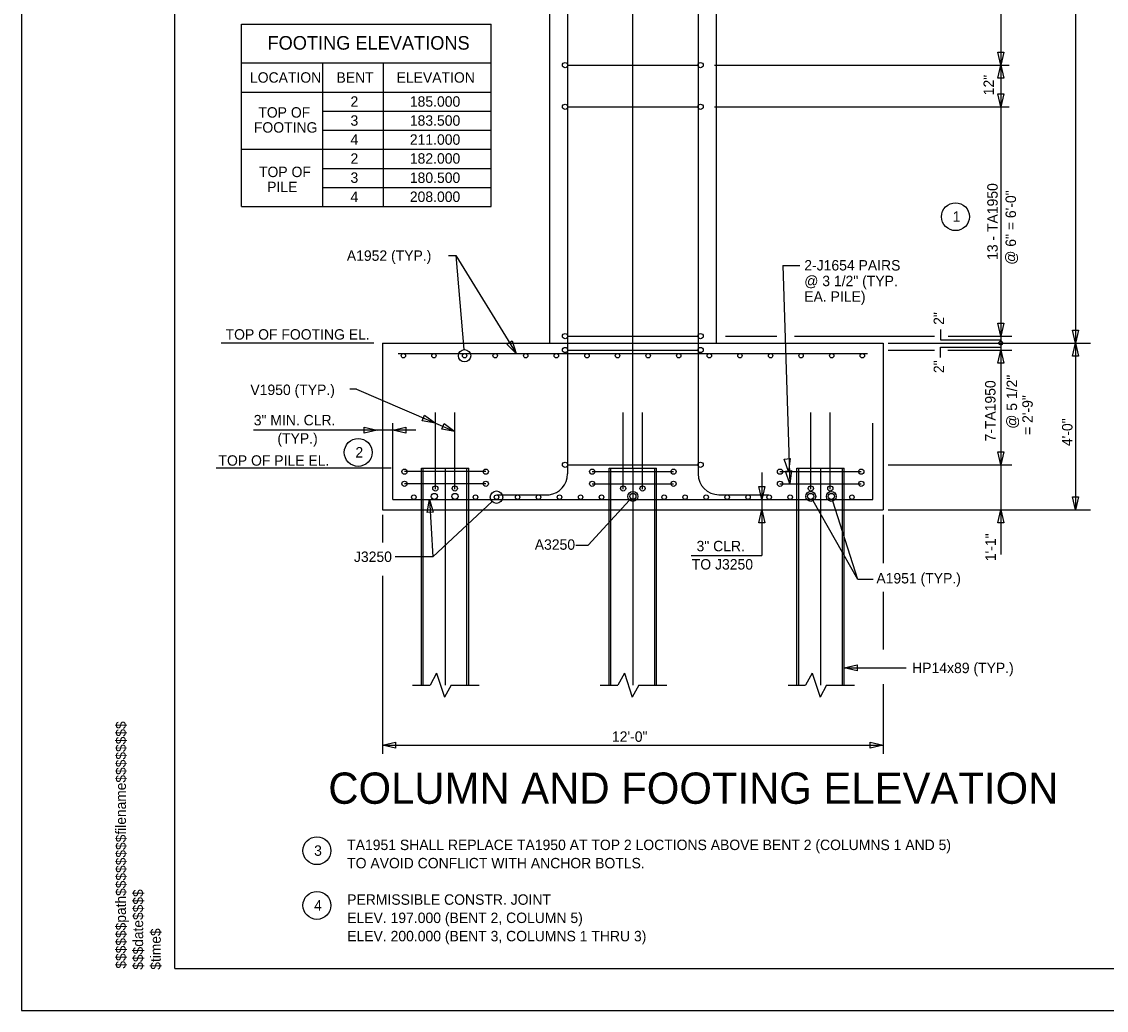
# Model space of a CAD drawing. Extents: x 1970675.2 to 1970711.3, y 796145.2 to 796167.2.
# Drawn here: x 1970675.24 to 1970688.23, y 796145.25 to 796157.1 of the extents above; entities that cross this region are included whole.
import ezdxf

# ---------------------------------------------------------------- set-up
doc = ezdxf.new("R2010")
doc.units = 0
for name, color, linetype in [('BR_AUTO DIMENSION', 7, 'Continuous'), ('BR_BORDER LINES', 7, 'Continuous'), ('BR_CENTER LINES', 7, 'Continuous'), ('BR_CONCRETE', 7, 'Continuous'), ('BR_REBAR', 7, 'Continuous'), ('BR_STRUCTURAL STEEL', 7, 'Continuous'), ('BR_TABLE LINES', 7, 'Continuous'), ('BR_TEXT', 7, 'Continuous'), ('Level 31', 7, 'Continuous'), ('RD_SHT_ID', 7, 'Continuous')]:
    doc.layers.add(name, color=color, linetype=linetype)

msp = doc.modelspace()

# ---------------------------------------------------------------- linework, layer by layer
at = {"layer": 'BR_AUTO DIMENSION'}
for p, q in [((1970686.97, 796164.857), (1970686.97, 796153.247)), ((1970687.866, 796162.732), (1970687.866, 796153.247)), ((1970683.541, 796156.581), (1970687.071, 796156.581)), ((1970683.541, 796156.081), (1970687.071, 796156.081)), ((1970680.352, 796154.299), (1970680.438, 796154.299)), ((1970680.438, 796154.299), (1970680.537, 796153.17)), ((1970680.438, 796154.299), (1970681.164, 796153.122)), ((1970684.356, 796154.176), (1970684.563, 796154.176)), ((1970684.356, 796154.176), (1970684.443, 796151.56)), ((1970686.247, 796153.41), (1970686.247, 796153.285)), ((1970679.456, 796153.247), (1970677.627, 796153.247)), ((1970683.669, 796153.331), (1970684.288, 796153.331)), ((1970684.499, 796153.331), (1970686.175, 796153.331)), ((1970685.621, 796153.247), (1970688.046, 796153.247)), ((1970686.247, 796153.285), (1970686.97, 796153.285)), ((1970686.34, 796153.331), (1970687.103, 796153.331)), ((1970686.97, 796153.247), (1970686.97, 796150.712)), ((1970687.866, 796153.247), (1970687.866, 796151.247)), ((1970685.621, 796153.164), (1970686.175, 796153.164)), ((1970686.247, 796153.074), (1970686.247, 796153.199)), ((1970686.247, 796153.199), (1970686.97, 796153.199)), ((1970686.335, 796153.164), (1970687.103, 796153.164)), ((1970679.25, 796152.695), (1970679.17, 796152.695)), ((1970679.25, 796152.695), (1970680.427, 796152.187)), ((1970679.959, 796152.203), (1970678.013, 796152.203)), ((1970679.666, 796151.747), (1970677.569, 796151.747)), ((1970684.106, 796151.695), (1970684.106, 796150.702)), ((1970684.106, 796151.695), (1970684.106, 796150.702)), ((1970685.621, 796151.789), (1970687.103, 796151.789)), ((1970686.97, 796151.747), (1970686.97, 796151.631)), ((1970680.123, 796151.372), (1970680.165, 796150.683)), ((1970680.873, 796151.349), (1970680.165, 796150.683)), ((1970682.024, 796150.825), (1970682.52, 796151.365)), ((1970685.258, 796150.414), (1970684.722, 796151.357)), ((1970685.258, 796150.414), (1970684.957, 796151.352)), ((1970679.561, 796151.187), (1970679.561, 796150.856)), ((1970685.561, 796151.187), (1970685.561, 796150.609)), ((1970685.621, 796151.247), (1970688.046, 796151.247)), ((1970681.879, 796150.825), (1970682.024, 796150.825)), ((1970680.165, 796150.683), (1970679.711, 796150.683)), ((1970683.258, 796150.702), (1970684.106, 796150.702)), ((1970683.265, 796150.702), (1970684.106, 796150.702)), ((1970679.561, 796150.458), (1970679.561, 796150.274)), ((1970685.441, 796150.414), (1970685.258, 796150.414)), ((1970679.561, 796150.274), (1970679.561, 796148.324)), ((1970685.561, 796150.263), (1970685.561, 796149.575)), ((1970685.094, 796149.355), (1970685.837, 796149.355)), ((1970680.209, 796149.288), (1970680.13, 796149.144)), ((1970680.209, 796149.288), (1970680.304, 796149)), ((1970682.459, 796149.288), (1970682.38, 796149.144)), ((1970682.459, 796149.288), (1970682.554, 796149)), ((1970684.709, 796149.288), (1970684.63, 796149.144)), ((1970684.709, 796149.288), (1970684.804, 796149)), ((1970679.92, 796149.144), (1970680.13, 796149.144)), ((1970680.382, 796149.144), (1970680.304, 796149)), ((1970680.382, 796149.144), (1970680.718, 796149.144)), ((1970682.17, 796149.144), (1970682.38, 796149.144)), ((1970682.632, 796149.144), (1970682.554, 796149)), ((1970682.632, 796149.144), (1970682.968, 796149.144)), ((1970684.42, 796149.144), (1970684.63, 796149.144)), ((1970684.882, 796149.144), (1970684.804, 796149)), ((1970684.882, 796149.144), (1970685.218, 796149.144)), ((1970685.561, 796149.158), (1970685.561, 796148.324)), ((1970679.561, 796148.426), (1970685.561, 796148.426))]:
    msp.add_line(p, q, dxfattribs=at)
for points in [[(1970687.006, 796156.737), (1970686.97, 796156.581), (1970686.934, 796156.737)], [(1970686.934, 796156.425), (1970686.97, 796156.581), (1970687.006, 796156.425)], [(1970687.006, 796156.237), (1970686.97, 796156.081), (1970686.934, 796156.237)], [(1970687.006, 796153.487), (1970686.97, 796153.331), (1970686.934, 796153.487)], [(1970687.902, 796153.403), (1970687.866, 796153.247), (1970687.83, 796153.403)], [(1970681.113, 796153.274), (1970681.164, 796153.122), (1970681.051, 796153.236)], [(1970687.83, 796153.091), (1970687.866, 796153.247), (1970687.902, 796153.091)], [(1970686.934, 796153.008), (1970686.97, 796153.164), (1970687.006, 796153.008)], [(1970680.065, 796152.382), (1970680.194, 796152.287), (1970680.036, 796152.316)], [(1970679.342, 796152.239), (1970679.498, 796152.203), (1970679.342, 796152.167)], [(1970679.842, 796152.167), (1970679.686, 796152.203), (1970679.842, 796152.239)], [(1970680.298, 796152.282), (1970680.427, 796152.187), (1970680.27, 796152.216)], [(1970687.006, 796151.945), (1970686.97, 796151.789), (1970686.934, 796151.945)], [(1970684.444, 796151.865), (1970684.426, 796151.706), (1970684.372, 796151.856)], [(1970684.461, 796151.719), (1970684.443, 796151.56), (1970684.389, 796151.71)], [(1970684.142, 796151.528), (1970684.106, 796151.372), (1970684.07, 796151.528)], [(1970680.096, 796151.214), (1970680.123, 796151.372), (1970680.168, 796151.219)], [(1970687.902, 796151.403), (1970687.866, 796151.247), (1970687.83, 796151.403)], [(1970684.07, 796151.091), (1970684.106, 796151.247), (1970684.142, 796151.091)], [(1970684.07, 796151.091), (1970684.106, 796151.247), (1970684.142, 796151.091)], [(1970686.934, 796151.091), (1970686.97, 796151.247), (1970687.006, 796151.091)], [(1970685.25, 796149.319), (1970685.094, 796149.355), (1970685.25, 796149.391)], [(1970679.717, 796148.39), (1970679.561, 796148.426), (1970679.717, 796148.462)], [(1970685.405, 796148.462), (1970685.561, 796148.426), (1970685.405, 796148.39)]]:
    msp.add_lwpolyline(points, close=True, dxfattribs=at)
for centre, radius in [((1970686.427, 796154.763), 0.167), ((1970686.97, 796153.247), 0.0235), ((1970679.269, 796151.936), 0.167), ((1970678.774, 796147.16), 0.167), ((1970678.774, 796146.504), 0.167)]:
    msp.add_circle(centre, radius, dxfattribs=at)
at = {"layer": 'BR_BORDER LINES'}
for q in [(1970677.07, 796166.746), (1970710.736, 796145.746)]:
    msp.add_line((1970677.07, 796145.746), q, dxfattribs=at)
at = {"layer": 'BR_CENTER LINES'}
for p, q in [((1970682.561, 796151.747), (1970682.561, 796166.409)), ((1970680.311, 796151.747), (1970680.311, 796149.144)), ((1970682.561, 796151.747), (1970682.561, 796149.144)), ((1970684.811, 796151.747), (1970684.811, 796149.144))]:
    msp.add_line(p, q, dxfattribs=at)
at = {"layer": 'BR_CONCRETE'}
for p, q in [((1970681.561, 796162.732), (1970681.561, 796153.247)), ((1970683.561, 796162.732), (1970683.561, 796153.247)), ((1970679.561, 796153.247), (1970685.561, 796153.247)), ((1970679.561, 796153.247), (1970679.561, 796151.247)), ((1970685.561, 796153.247), (1970685.561, 796151.247)), ((1970679.561, 796151.247), (1970685.561, 796151.247))]:
    msp.add_line(p, q, dxfattribs=at)
at = {"layer": 'BR_REBAR'}
for p, q in [((1970681.779, 796164.961), (1970681.779, 796154.623)), ((1970683.342, 796164.959), (1970683.342, 796151.679)), ((1970681.779, 796156.581), (1970683.342, 796156.581)), ((1970681.779, 796156.081), (1970683.342, 796156.081)), ((1970681.779, 796154.623), (1970681.779, 796151.678)), ((1970681.779, 796153.331), (1970683.342, 796153.331)), ((1970679.748, 796153.122), (1970685.373, 796153.122)), ((1970681.779, 796153.164), (1970683.342, 796153.164)), ((1970680.194, 796151.497), (1970680.194, 796152.417)), ((1970680.427, 796151.497), (1970680.427, 796152.417)), ((1970682.444, 796151.497), (1970682.444, 796152.417)), ((1970682.677, 796151.497), (1970682.677, 796152.417)), ((1970684.694, 796151.497), (1970684.694, 796152.417)), ((1970684.927, 796151.497), (1970684.927, 796152.417)), ((1970679.686, 796151.372), (1970679.686, 796152.289)), ((1970685.436, 796151.372), (1970685.436, 796152.289)), ((1970680.798, 796151.706), (1970679.824, 796151.706)), ((1970681.779, 796151.788), (1970683.342, 796151.788)), ((1970682.074, 796151.706), (1970683.048, 796151.706)), ((1970684.324, 796151.706), (1970685.298, 796151.706)), ((1970680.798, 796151.56), (1970679.824, 796151.56)), ((1970682.074, 796151.56), (1970683.048, 796151.56)), ((1970684.324, 796151.56), (1970685.298, 796151.56)), ((1970680.936, 796151.429), (1970681.557, 796151.429)), ((1970683.592, 796151.429), (1970684.185, 796151.429)), ((1970679.686, 796151.372), (1970685.436, 796151.372))]:
    msp.add_line(p, q, dxfattribs=at)
for centre, radius in [((1970681.748, 796156.581), 0.0313), ((1970683.373, 796156.581), 0.0313), ((1970681.748, 796156.081), 0.0313), ((1970683.373, 796156.081), 0.0313), ((1970681.748, 796153.331), 0.0313), ((1970683.373, 796153.331), 0.0313), ((1970679.811, 796153.096), 0.0265), ((1970680.177, 796153.096), 0.0265), ((1970680.544, 796153.096), 0.0265), ((1970680.911, 796153.096), 0.0265), ((1970681.277, 796153.096), 0.0265), ((1970681.644, 796153.096), 0.0265), ((1970681.748, 796153.164), 0.0313), ((1970682.011, 796153.096), 0.0265), ((1970682.377, 796153.096), 0.0265), ((1970682.744, 796153.096), 0.0265), ((1970683.111, 796153.096), 0.0265), ((1970683.373, 796153.164), 0.0313), ((1970683.477, 796153.096), 0.0265), ((1970683.844, 796153.096), 0.0265), ((1970684.211, 796153.096), 0.0265), ((1970684.577, 796153.096), 0.0265), ((1970684.944, 796153.096), 0.0265), ((1970685.311, 796153.096), 0.0265), ((1970685.311, 796153.096), 0.0265), ((1970681.748, 796151.788), 0.0313), ((1970683.373, 796151.788), 0.0313), ((1970679.824, 796151.706), 0.0313), ((1970680.798, 796151.706), 0.0313), ((1970682.074, 796151.706), 0.0313), ((1970683.048, 796151.706), 0.0313), ((1970684.324, 796151.706), 0.0313), ((1970685.298, 796151.706), 0.0313), ((1970679.824, 796151.56), 0.0313), ((1970680.798, 796151.56), 0.0313), ((1970682.074, 796151.56), 0.0313), ((1970683.048, 796151.56), 0.0313), ((1970684.324, 796151.56), 0.0313), ((1970685.298, 796151.56), 0.0313), ((1970679.936, 796151.4), 0.0265), ((1970680.182, 796151.409), 0.0366), ((1970680.194, 796151.504), 0.0313), ((1970680.429, 796151.409), 0.0366), ((1970680.427, 796151.504), 0.0313), ((1970680.675, 796151.4), 0.0265), ((1970680.927, 796151.4), 0.0265), ((1970681.179, 796151.4), 0.0265), ((1970681.43, 796151.4), 0.0265), ((1970681.682, 796151.4), 0.0265), ((1970681.934, 796151.4), 0.0265), ((1970682.186, 796151.4), 0.0265), ((1970682.185, 796151.4), 0.0265), ((1970682.444, 796151.504), 0.0313), ((1970682.561, 796151.409), 0.0366), ((1970682.677, 796151.504), 0.0313), ((1970682.936, 796151.4), 0.0265), ((1970683.187, 796151.4), 0.0265), ((1970683.439, 796151.4), 0.0265), ((1970683.691, 796151.4), 0.0265), ((1970683.942, 796151.4), 0.0265), ((1970684.194, 796151.4), 0.0265), ((1970684.446, 796151.4), 0.0265), ((1970684.446, 796151.4), 0.0265), ((1970684.692, 796151.409), 0.0366), ((1970684.694, 796151.504), 0.0313), ((1970684.927, 796151.504), 0.0313), ((1970684.939, 796151.409), 0.0366), ((1970685.186, 796151.4), 0.0265)]:
    msp.add_circle(centre, radius, dxfattribs=at)
for centre, start, end in [((1970681.529, 796151.678), 276.3821, 360), ((1970683.592, 796151.679), 180, 270)]:
    msp.add_arc(centre, 0.25, start, end, dxfattribs=at)
at = {"layer": 'BR_STRUCTURAL STEEL'}
for p, q in [((1970680.027, 796151.247), (1970680.027, 796151.747)), ((1970680.027, 796151.747), (1970680.594, 796151.747)), ((1970680.048, 796151.247), (1970680.048, 796151.747)), ((1970680.573, 796151.247), (1970680.573, 796151.747)), ((1970680.594, 796151.247), (1970680.594, 796151.747)), ((1970682.277, 796151.747), (1970682.844, 796151.747)), ((1970682.277, 796151.247), (1970682.277, 796151.747)), ((1970682.298, 796151.247), (1970682.298, 796151.747)), ((1970682.823, 796151.247), (1970682.823, 796151.747)), ((1970682.844, 796151.247), (1970682.844, 796151.747)), ((1970684.527, 796151.247), (1970684.527, 796151.747)), ((1970684.527, 796151.747), (1970685.094, 796151.747)), ((1970684.548, 796151.247), (1970684.548, 796151.747)), ((1970685.073, 796151.247), (1970685.073, 796151.747)), ((1970685.094, 796151.247), (1970685.094, 796151.747)), ((1970680.027, 796149.144), (1970680.027, 796151.247)), ((1970680.048, 796149.144), (1970680.048, 796151.247)), ((1970680.573, 796149.144), (1970680.573, 796151.247)), ((1970680.594, 796149.144), (1970680.594, 796151.247)), ((1970682.277, 796149.144), (1970682.277, 796151.247)), ((1970682.298, 796149.144), (1970682.298, 796151.247)), ((1970682.823, 796149.144), (1970682.823, 796151.247)), ((1970682.844, 796149.144), (1970682.844, 796151.247)), ((1970684.527, 796149.144), (1970684.527, 796151.247)), ((1970684.548, 796149.144), (1970684.548, 796151.247)), ((1970685.073, 796149.144), (1970685.073, 796151.247)), ((1970685.094, 796149.144), (1970685.094, 796151.247))]:
    msp.add_line(p, q, dxfattribs=at)
at = {"layer": 'BR_TABLE LINES'}
for p, q in [((1970677.869, 796157.072), (1970680.862, 796157.072)), ((1970677.869, 796154.886), (1970677.869, 796157.072)), ((1970680.862, 796154.886), (1970680.862, 796157.072)), ((1970677.869, 796156.607), (1970680.862, 796156.607)), ((1970678.847, 796154.886), (1970678.847, 796156.607)), ((1970679.573, 796154.886), (1970679.573, 796156.607)), ((1970677.869, 796156.257), (1970680.862, 796156.257)), ((1970678.847, 796156.028), (1970680.862, 796156.028)), ((1970678.847, 796155.8), (1970680.862, 796155.8)), ((1970677.869, 796155.573), (1970680.862, 796155.573)), ((1970678.847, 796155.573), (1970680.862, 796155.573)), ((1970678.847, 796155.342), (1970680.862, 796155.342)), ((1970678.847, 796155.113), (1970680.862, 796155.113)), ((1970677.869, 796154.886), (1970680.862, 796154.886))]:
    msp.add_line(p, q, dxfattribs=at)
at = {"layer": 'BR_TEXT'}
for centre, radius in [((1970680.544, 796153.096), 0.0744), ((1970680.927, 796151.4), 0.0744), ((1970682.561, 796151.409), 0.0595), ((1970684.692, 796151.409), 0.0595), ((1970684.939, 796151.409), 0.0595)]:
    msp.add_circle(centre, radius, dxfattribs=at)
at = {"layer": 'Level 31'}
msp.add_lwpolyline([(1970675.236, 796145.246), (1970711.236, 796145.246), (1970711.236, 796167.246), (1970675.236, 796167.246)], close=True, dxfattribs=at)

# ---------------------------------------------------------------- texts
at = {"layer": 'BR_TEXT'}
for s, height, p in [('FOOTING ELEVATIONS', 0.16305, (1970678.182, 796156.766)), ('LOCATION', 0.125, (1970677.972, 796156.37)), ('BENT', 0.125, (1970679.009, 796156.37)), ('ELEVATION', 0.125, (1970679.729, 796156.37)), ('2', 0.125, (1970679.177, 796156.082)), ('185.000', 0.125, (1970679.888, 796156.082)), ('TOP OF ', 0.125, (1970678.072, 796155.951)), ('3', 0.125, (1970679.177, 796155.854)), ('183.500', 0.125, (1970679.888, 796155.854)), ('FOOTING', 0.125, (1970678.019, 796155.771)), ('4', 0.125, (1970679.177, 796155.627)), ('211.000', 0.125, (1970679.888, 796155.626)), ('2', 0.125, (1970679.177, 796155.398)), ('182.000', 0.125, (1970679.888, 796155.399)), ('TOP OF', 0.125, (1970678.08, 796155.238)), ('3', 0.125, (1970679.177, 796155.169)), ('180.500', 0.125, (1970679.888, 796155.168)), ('PILE', 0.125, (1970678.178, 796155.058)), ('4', 0.125, (1970679.177, 796154.94)), ('208.000', 0.125, (1970679.888, 796154.94)), ('1', 0.125, (1970686.394, 796154.702)), ('A1952 (TYP.)', 0.125, (1970679.133, 796154.234)), ('2-J1654 PAIRS', 0.125, (1970684.615, 796154.118)), ('@ 3 1/2" (TYP.', 0.125, (1970684.615, 796153.93)), ('EA. PILE)', 0.125, (1970684.615, 796153.743)), ('TOP OF FOOTING EL.', 0.125, (1970677.68, 796153.289)), ('V1950 (TYP.)', 0.125, (1970677.977, 796152.625)), (' 3" MIN. CLR.', 0.125, (1970677.971, 796152.261)), ('(TYP.)', 0.125, (1970678.301, 796152.042)), ('2', 0.125, (1970679.236, 796151.875)), ('TOP OF PILE EL.', 0.125, (1970677.595, 796151.777)), ('A3250', 0.125, (1970681.385, 796150.769)), ('3" CLR.', 0.125, (1970683.324, 796150.751)), ('J3250', 0.125, (1970679.218, 796150.623)), ('TO J3250', 0.125, (1970683.267, 796150.532)), ('A1951 (TYP.)', 0.125, (1970685.479, 796150.365)), ('HP14x89 (TYP.)', 0.125, (1970685.908, 796149.29)), ('12\'-0"', 0.125, (1970682.31, 796148.466)), ('COLUMN AND FOOTING ELEVATION', 0.375, (1970678.911, 796147.723)), ('TA1951 SHALL REPLACE TA1950 AT TOP 2 LOCTIONS ABOVE BENT 2 (COLUMNS 1 AND 5)', 0.125, (1970679.137, 796147.168)), ('3', 0.125, (1970678.741, 796147.099)), ('TO AVOID CONFLICT WITH ANCHOR BOTLS. ', 0.125, (1970679.137, 796146.949)), ('PERMISSIBLE CONSTR. JOINT ', 0.125, (1970679.137, 796146.512)), ('4', 0.125, (1970678.741, 796146.443)), ('ELEV. 197.000 (BENT 2, COLUMN 5)', 0.125, (1970679.137, 796146.293)), ('ELEV. 200.000 (BENT 3, COLUMNS 1 THRU 3)', 0.125, (1970679.137, 796146.074))]:
    msp.add_text(s, height=height, dxfattribs=at).set_placement(p)
for s, p in [('12"', (1970686.888, 796156.219)), ('13 - TA1950', (1970686.933, 796154.245)), ('@ 6" = 6\'-0"', (1970687.152, 796154.187)), ('2"', (1970686.29, 796153.466)), ('2"', (1970686.291, 796152.888)), ('@ 5 1/2"', (1970687.165, 796152.22)), ('7-TA1950', (1970686.907, 796152.067)), ('= 2\'-9"', (1970687.353, 796152.146)), ('4\'-0"', (1970687.829, 796152.012)), ('1\'-1"', (1970686.911, 796150.632))]:
    msp.add_text(s, height=0.125, rotation=90, dxfattribs=at).set_placement(p)
at = {"layer": 'RD_SHT_ID'}
for s, height, p in [('$$$$$$path$$$$$$$$filename$$$$$$$$', 0.12347, (1970676.486, 796145.746)), ('$$$date$$$$', 0.12347, (1970676.692, 796145.733)), ('$time$', 0.1235, (1970676.903, 796145.733))]:
    msp.add_text(s, height=height, rotation=90, dxfattribs=at).set_placement(p)

doc.saveas('drawing.dxf')
